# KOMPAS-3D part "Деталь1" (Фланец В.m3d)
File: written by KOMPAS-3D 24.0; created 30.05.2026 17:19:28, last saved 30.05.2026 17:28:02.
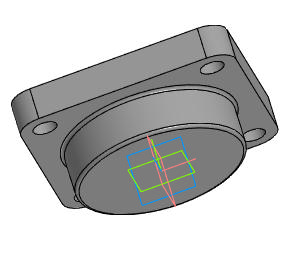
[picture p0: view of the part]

Document properties: Автор: R2D2; Полное имя файла: E:\Работа\Зайцев\GVWR2434M-2W-F-ОСТ Задвижка клиновая с выдвижным штоком DN.ru Ду50-300 Ру25\исходные материалы\DN300\Деталь1 Деталь1_1.m3d

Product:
- Part/product: Деталь1
    additional columns: Типовые

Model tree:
1. Эскиз:2
2. Элемент выдавливания:1
     Расстояние 1 = 40
3. Эскиз:3  (with: Грань.Элемент выдавливания:1)
4. Элемент выдавливания:2
     Расстояние 1 = 30
5. Эскиз:4  (with: Грань.Элемент выдавливания:2)
6. Элемент выдавливания:3
     Расстояние 2 = 70
7. Массив по концентрической сетке:1  (with: Элемент выдавливания:3, Эскиз:4, Грань.Элемент выдавливания:1)  (4 pattern instances)
     Шаг 2 = 360
8. Эскиз:5  (with: Грань.Элемент выдавливания:2)
9. Элемент выдавливания:4
     Расстояние 1 = 10
10. Эскиз:6  (with: Грань.Элемент выдавливания:4)
11. Элемент выдавливания:5
     Расстояние 1 = 10
12. Массив по концентрической сетке:2  (with: Элемент выдавливания:5, Эскиз:6, Грань.Элемент выдавливания:1)  (5 pattern instances)
     Шаг 2 = 360
13. Эскиз:7  (with: Грань.Элемент выдавливания:4)
14. Элемент выдавливания:6
     Расстояние 2 = 30
15. Скругление:1  (with: Ребро.Элемент выдавливания:2)
     Радиус = 22
16. Скругление:2  (with: Ребро.Элемент выдавливания:2, Ребро.Элемент выдавливания:1)
     Радиус = 3

Expressions: 70/2; 84/2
